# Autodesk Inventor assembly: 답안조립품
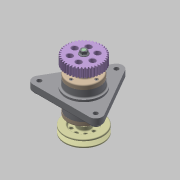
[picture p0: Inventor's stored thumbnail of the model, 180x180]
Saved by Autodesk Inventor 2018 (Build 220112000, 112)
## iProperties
Created: 2023-04
Part Number: 답안조립품
Material: 일반
Document SubType Name: Assembly
Designer: home
Author: home
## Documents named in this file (11)
- C:\Users\kimgi\Desktop\730407V1020\답안조립품.iam
- C:\Users\kimgi\Desktop\730407V1020\본체.ipt
- C:\Users\kimgi\Desktop\730407V1020\베어링 6204.ipt
- C:\Users\kimgi\Desktop\730407V1020\축.ipt
- C:\Users\kimgi\Desktop\730407V1020\커버.ipt
- C:\Users\kimgi\Desktop\730407V1020\볼트 M4 x 12.ipt
- C:\Users\kimgi\Desktop\730407V1020\오일 실 20 32 8.ipt
- C:\Users\kimgi\Desktop\730407V1020\묻힘키 5x5x16.ipt
- C:\Users\kimgi\Desktop\730407V1020\v-벨트풀리.ipt
- C:\Users\kimgi\Desktop\730407V1020\스퍼기어.ipt
- C:\Users\kimgi\Desktop\730407V1020\6각 플랜지 너트 M10.ipt
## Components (3 placed, 2 different names)
1. v-벨트풀리:1
2. 6각 플랜지 너트 M10:1
3. 6각 플랜지 너트 M10:2
